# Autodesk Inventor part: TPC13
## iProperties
Shininess: 64.0
Length Units: 11272
Angle Units: 11279
Time Units: 11290
Mass Units: 11286
Length Display Precision: 3
Angle Display Precision: 2
Compacted: True
Part Number: TPC13
Document SubType Name: Modeling
Created: 2004-08
Designer: Lori
Manufacturer: Standard
Standards Organization: Custom
Density: 0.0
Volumn: 0.0
Area: 0.0
PropertySet Name: Model Information
Control State: 0
Master: False
Checked Out: False
Author: Lori
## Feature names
1. Base1
